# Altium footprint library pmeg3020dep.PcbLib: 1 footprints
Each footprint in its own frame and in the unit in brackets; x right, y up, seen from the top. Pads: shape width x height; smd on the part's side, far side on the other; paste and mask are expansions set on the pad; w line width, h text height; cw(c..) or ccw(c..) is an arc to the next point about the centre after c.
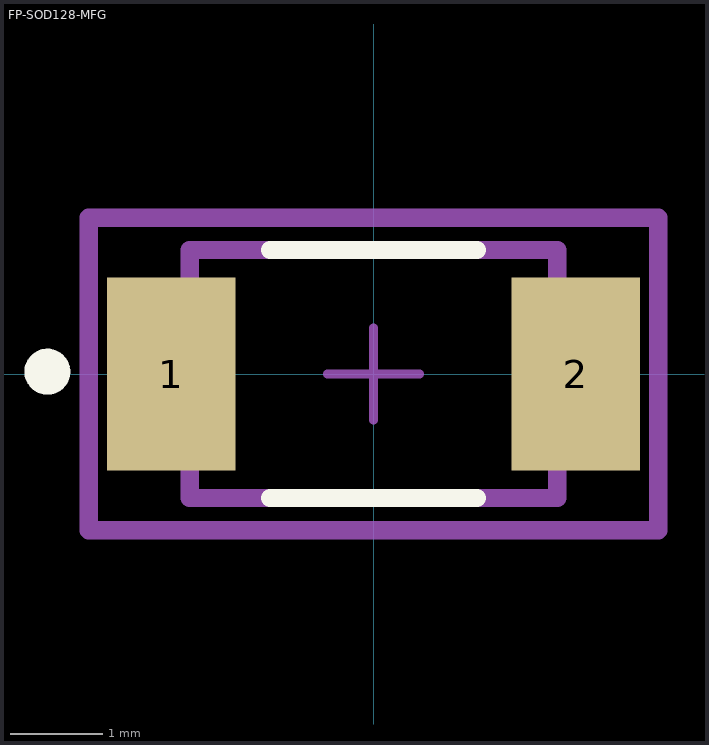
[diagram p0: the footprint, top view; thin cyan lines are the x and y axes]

## FP-SOD128-MFG [mm]
pads (2):
  rect 1.4x2.1 smd paste-1000 mask+0: 1(-2.2,0) 2(2.2,0)
Top Overlay:
  circle w0.25: c-3.55,0.025 r0.125
  lines w0.2: -1.125,-1.35 1.125,-1.35 ; -1.125,1.35 1.125,1.35
Top Paste:
  rectangle: -2.8,-0.95 -1.6,0.95
  rectangle: 1.6,-0.95 2.8,0.95
Mechanical 5:
  lines w0.2: -3.1,-1.7 3.1,-1.7 3.1,1.7 -3.1,1.7 -3.1,-1.7
  text ".Designator" at 0,0.188 h1
Mechanical 13:
  lines w0.2: -2,-1.35 2,-1.35 2,1.35 -2,1.35 -2,-1.35
Mechanical 15:
  lines w0.2: -3.1,-1.7 3.1,-1.7 3.1,1.7 -3.1,1.7 -3.1,-1.7
Mechanical 16:
  lines w0.1: -0.5,0 0.5,0 ; 0,-0.5 0,0.5
3D body "Diode_Nexperia_PMEG40T50EPX_eec.STEP": height 0.25, standoff 0, extent -3.1,-1.7 3.1,1.7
